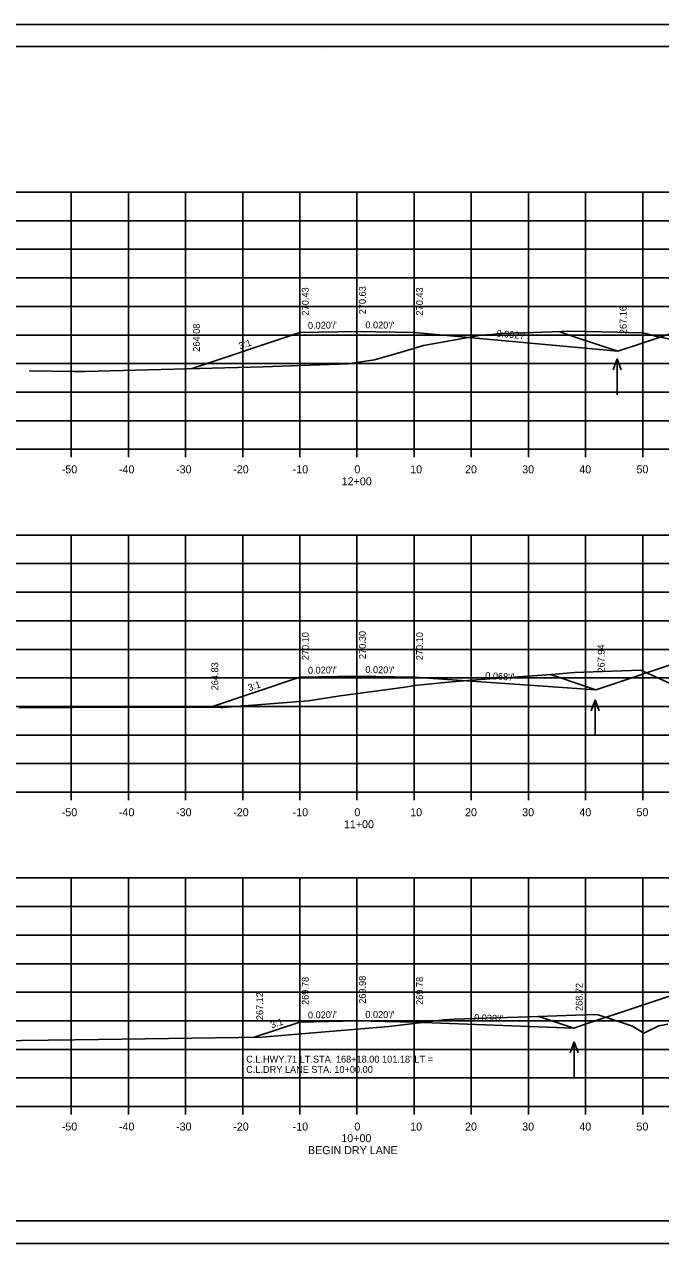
# Model space of a CAD drawing. Extents: x 285 to 4233, y -659 to 3710.
# Drawn here: x 4012.2 to 4123.5, y -579.2 to -365.9 of the extents above; entities that cross this region are included whole.
import ezdxf

# ---------------------------------------------------------------- set-up
doc = ezdxf.new("R2010")
doc.units = 0
for name, color, linetype in [('R_Axis', 7, 'Continuous'), ('R_Axis Annot', 7, 'Continuous'), ('R_Border', 7, 'Continuous'), ('R_Dimension', 7, 'Continuous'), ('R_Exist Surface', 7, 'Continuous'), ('R_Fin Surface', 7, 'Continuous'), ('R_Grid', 7, 'Continuous'), ('R_No Plot', 7, 'Continuous'), ('R_Water Annot', 7, 'Continuous'), ('R_Xsect Elev', 7, 'Continuous'), ('R_Xsect Slope', 7, 'Continuous')]:
    doc.layers.add(name, color=color, linetype=linetype)

msp = doc.modelspace()

# ---------------------------------------------------------------- linework, layer by layer
at = {"layer": 'R_Axis'}
for p, q in [((3920.38, -440.26), (4220.38, -440.26)), ((4020.38, -441.66), (4020.38, -440.26)), ((4030.38, -441.66), (4030.38, -440.26)), ((4040.38, -441.66), (4040.38, -440.26)), ((4050.38, -441.66), (4050.38, -440.26)), ((4060.38, -441.66), (4060.38, -440.26)), ((4070.38, -441.66), (4070.38, -440.26)), ((4080.38, -441.66), (4080.38, -440.26)), ((4090.38, -441.66), (4090.38, -440.26)), ((4100.38, -441.66), (4100.38, -440.26)), ((4110.38, -441.66), (4110.38, -440.26)), ((4120.38, -441.66), (4120.38, -440.26)), ((3920.38, -500.26), (4220.38, -500.26)), ((4020.38, -501.66), (4020.38, -500.26)), ((4030.38, -501.66), (4030.38, -500.26)), ((4040.38, -501.66), (4040.38, -500.26)), ((4050.38, -501.66), (4050.38, -500.26)), ((4060.38, -501.66), (4060.38, -500.26)), ((4070.38, -501.66), (4070.38, -500.26)), ((4080.38, -501.66), (4080.38, -500.26)), ((4090.38, -501.66), (4090.38, -500.26)), ((4100.38, -501.66), (4100.38, -500.26)), ((4110.38, -501.66), (4110.38, -500.26)), ((4120.38, -501.66), (4120.38, -500.26)), ((3920.38, -555.26), (4220.38, -555.26)), ((4020.38, -556.66), (4020.38, -555.26)), ((4030.38, -556.66), (4030.38, -555.26)), ((4040.38, -556.66), (4040.38, -555.26)), ((4050.38, -556.66), (4050.38, -555.26)), ((4060.38, -556.66), (4060.38, -555.26)), ((4070.38, -556.66), (4070.38, -555.26)), ((4080.38, -556.66), (4080.38, -555.26)), ((4090.38, -556.66), (4090.38, -555.26)), ((4100.38, -556.66), (4100.38, -555.26)), ((4110.38, -556.66), (4110.38, -555.26)), ((4120.38, -556.66), (4120.38, -555.26))]:
    msp.add_line(p, q, dxfattribs=at)
at = {"layer": 'R_Border'}
for p, q in [((3912.38, -369.8), (4228.56, -369.8)), ((4064.9, -370.06), (4064.9, -370.06)), ((4064.9, -370.06), (4064.9, -370.06)), ((4228.56, -575.26), (3912.38, -575.26))]:
    msp.add_line(p, q, dxfattribs=at)
at = {"layer": 'R_Exist Surface'}
for points in [[(4013.03, -426.54), (4020.86, -426.65), (4022.74, -426.67), (4053.98, -425.84), (4068.84, -425.28), (4071.04, -424.95), (4073.44, -424.61), (4078.09, -423.23), (4082, -422.11), (4088.89, -420.86), (4092.09, -420.31), (4093.92, -420.18), (4095.42, -419.97), (4101.32, -419.79), (4107.72, -419.6), (4115.91, -419.78), (4119.75, -419.85), (4120.2, -419.84), (4122.88, -420.53), (4131.19, -422.2)], [(4011.22, -485.44), (4020.63, -485.44), (4039.24, -485.38), (4046.57, -485.45), (4046.91, -485.42), (4061.87, -484.29), (4067.01, -483.45), (4077.08, -482.13), (4079.15, -481.79), (4080.47, -481.57), (4086.99, -480.96), (4091.29, -480.6), (4092.01, -480.55), (4104.42, -479.65), (4108.43, -479.32), (4110.06, -479.25), (4120.03, -478.92), (4122.49, -480.01), (4128.08, -482.59)], [(3997.6, -543.9), (4021.01, -543.58), (4053.78, -543.12), (4056.49, -542.88), (4075.95, -541.28), (4079.41, -540.84), (4085.58, -540.07), (4087.42, -539.99), (4090.99, -539.83), (4100.42, -539.56), (4111.94, -539.14), (4112.59, -539.22), (4115.09, -540.03), (4118.27, -541.08), (4118.41, -541.12), (4118.5, -541.15), (4120.58, -542.4), (4120.69, -542.36), (4123.2, -541.11), (4124.78, -540.84)]]:
    msp.add_lwpolyline(points, dxfattribs=at)
at = {"layer": 'R_Fin Surface'}
for points in [[(4105.7, -419.66), (4108.91, -420.73), (4116.01, -423.1), (4119.4, -421.97), (4142.06, -414.43), (4151.54, -412.86), (4162.1, -411.1), (4164.59, -411), (4170.11, -410.78), (4171.67, -410.75), (4172.12, -410.74), (4176.16, -410.66), (4189.76, -410.39), (4196.16, -410.26), (4196.68, -410.28), (4202.18, -410.5), (4217.15, -412.99), (4220.38, -413.53)], [(4041.34, -426.18), (4060.38, -419.83), (4070.38, -419.63), (4080.38, -419.83), (4116.01, -423.1)], [(4104.21, -479.67), (4105.82, -480.2), (4112.16, -482.32), (4114.8, -481.44), (4135.87, -474.43), (4145.96, -472.75), (4155.9, -471.1), (4158.68, -470.99), (4163.92, -470.78), (4165.4, -470.75), (4165.92, -470.74), (4170.68, -470.64), (4186.67, -470.32), (4189.97, -470.26), (4190.23, -470.27), (4195.98, -470.5), (4199.51, -471.09), (4218.21, -474.2)], [(4044.55, -485.43), (4060.38, -480.15), (4070.38, -479.95), (4080.38, -480.15), (4112.16, -482.32)], [(4102.17, -539.49), (4102.72, -539.68), (4108.31, -541.54), (4110.32, -540.87), (4129.67, -534.43), (4140.37, -532.65), (4149.71, -531.1), (4152.76, -530.98), (4157.72, -530.78), (4159.12, -530.75), (4159.73, -530.74), (4165.19, -530.63), (4183.57, -530.26), (4183.77, -530.26), (4183.79, -530.26), (4189.78, -530.5), (4192.25, -530.91), (4212.81, -534.33)], [(4052.41, -543.14), (4060.38, -540.48), (4070.38, -540.28), (4080.38, -540.48), (4108.31, -541.54)]]:
    msp.add_lwpolyline(points, dxfattribs=at)
at = {"layer": 'R_Grid'}
for p, q in [((3920.38, -395.26), (4220.38, -395.26)), ((4020.38, -440.26), (4020.38, -395.26)), ((4030.38, -440.26), (4030.38, -395.26)), ((4040.38, -440.26), (4040.38, -395.26)), ((4050.38, -440.26), (4050.38, -395.26)), ((4060.38, -440.26), (4060.38, -395.26)), ((4070.38, -440.26), (4070.38, -395.26)), ((4080.38, -440.26), (4080.38, -395.26)), ((4090.38, -440.26), (4090.38, -395.26)), ((4100.38, -440.26), (4100.38, -395.26)), ((4110.38, -440.26), (4110.38, -395.26)), ((4120.38, -440.26), (4120.38, -395.26)), ((3920.38, -400.26), (4220.38, -400.26)), ((3920.38, -405.26), (4220.38, -405.26)), ((3920.38, -410.26), (4220.38, -410.26)), ((3920.38, -415.26), (4220.38, -415.26)), ((3920.38, -420.26), (4220.38, -420.26)), ((3920.38, -425.26), (4220.38, -425.26)), ((3920.38, -430.26), (4220.38, -430.26)), ((3920.38, -435.26), (4220.38, -435.26)), ((3920.38, -440.26), (4220.38, -440.26)), ((3920.38, -455.26), (4220.38, -455.26)), ((4020.38, -500.26), (4020.38, -455.26)), ((4030.38, -500.26), (4030.38, -455.26)), ((4040.38, -500.26), (4040.38, -455.26)), ((4050.38, -500.26), (4050.38, -455.26)), ((4060.38, -500.26), (4060.38, -455.26)), ((4070.38, -500.26), (4070.38, -455.26)), ((4080.38, -500.26), (4080.38, -455.26)), ((4090.38, -500.26), (4090.38, -455.26)), ((4100.38, -500.26), (4100.38, -455.26)), ((4110.38, -500.26), (4110.38, -455.26)), ((4120.38, -500.26), (4120.38, -455.26)), ((3920.38, -460.26), (4220.38, -460.26)), ((3920.38, -465.26), (4220.38, -465.26)), ((3920.38, -470.26), (4220.38, -470.26)), ((3920.38, -475.26), (4220.38, -475.26)), ((3920.38, -480.26), (4220.38, -480.26)), ((3920.38, -485.26), (4220.38, -485.26)), ((3920.38, -490.26), (4220.38, -490.26)), ((3920.38, -495.26), (4220.38, -495.26)), ((3920.38, -500.26), (4220.38, -500.26)), ((3920.38, -515.26), (4220.38, -515.26)), ((4020.38, -555.26), (4020.38, -515.26)), ((4030.38, -555.26), (4030.38, -515.26)), ((4040.38, -555.26), (4040.38, -515.26)), ((4050.38, -555.26), (4050.38, -515.26)), ((4060.38, -555.26), (4060.38, -515.26)), ((4070.38, -555.26), (4070.38, -515.26)), ((4080.38, -555.26), (4080.38, -515.26)), ((4090.38, -555.26), (4090.38, -515.26)), ((4100.38, -555.26), (4100.38, -515.26)), ((4110.38, -555.26), (4110.38, -515.26)), ((4120.38, -555.26), (4120.38, -515.26)), ((3920.38, -520.26), (4220.38, -520.26)), ((3920.38, -525.26), (4220.38, -525.26)), ((3920.38, -530.26), (4220.38, -530.26)), ((3920.38, -535.26), (4220.38, -535.26)), ((3920.38, -540.26), (4220.38, -540.26)), ((3920.38, -545.26), (4220.38, -545.26)), ((3920.38, -550.26), (4220.38, -550.26)), ((3920.38, -555.26), (4220.38, -555.26))]:
    msp.add_line(p, q, dxfattribs=at)
at = {"layer": 'R_No Plot'}
for p, q in [((3899.98, -365.9), (4233.31, -365.9)), ((3899.98, -579.24), (4233.31, -579.24))]:
    msp.add_line(p, q, dxfattribs=at)
for points in [[(3899.97, -365.9), (4233.31, -365.9), (4233.31, -579.24), (3899.97, -579.24)], [(4146.3, -369.8), (4165.92, -369.8), (4165.92, -379.68), (4182.03, -379.68), (4205.23, -379.68), (4205.35, -407.84), (4228.56, -407.84), (4228.56, -575.26), (3912.38, -575.26), (3912.38, -369.8)]]:
    msp.add_lwpolyline(points, close=True, dxfattribs=at)
at = {"layer": 'R_Water Annot'}
for p, q in [((4115.94, -424.42), (4115.24, -426.34)), ((4115.94, -430.7), (4115.94, -424.42)), ((4115.94, -424.42), (4116.64, -426.34)), ((4112.08, -484.11), (4111.38, -486.04)), ((4112.08, -490.4), (4112.08, -484.11)), ((4112.08, -484.11), (4112.78, -486.04)), ((4108.36, -543.91), (4107.66, -545.83)), ((4108.36, -550.19), (4108.36, -543.91)), ((4108.36, -543.91), (4109.06, -545.83))]:
    msp.add_line(p, q, dxfattribs=at)

# ---------------------------------------------------------------- texts
at = {"layer": 'R_Axis Annot'}
for s, p in [('-50', (4018.72, -444.46)), ('-40', (4028.72, -444.46)), ('-30', (4038.72, -444.46)), ('-20', (4048.72, -444.46)), ('-10', (4059.12, -444.46)), ('0', (4069.92, -444.46)), ('10', (4079.69, -444.46)), ('20', (4089.29, -444.46)), ('30', (4099.29, -444.46)), ('40', (4109.29, -444.46)), ('50', (4119.29, -444.46)), ('12+00', (4067.7, -446.56)), ('-50', (4018.72, -504.46)), ('-40', (4028.72, -504.46)), ('-30', (4038.72, -504.46)), ('-20', (4048.72, -504.46)), ('-10', (4059.12, -504.46)), ('0', (4069.92, -504.46)), ('10', (4079.69, -504.46)), ('20', (4089.29, -504.46)), ('30', (4099.29, -504.46)), ('40', (4109.29, -504.46)), ('50', (4119.29, -504.46)), ('11+00', (4068.09, -506.56)), ('-50', (4018.72, -559.46)), ('-40', (4028.72, -559.46)), ('-30', (4038.72, -559.46)), ('-20', (4048.72, -559.46)), ('-10', (4059.12, -559.46)), ('0', (4069.92, -559.46)), ('10', (4079.69, -559.46)), ('20', (4089.29, -559.46)), ('30', (4099.29, -559.46)), ('40', (4109.29, -559.46)), ('50', (4119.29, -559.46)), ('10+00', (4067.64, -561.49)), ('BEGIN DRY LANE', (4061.8, -563.59))]:
    msp.add_text(s, height=1.4, dxfattribs=at).set_placement(p)
at = {"layer": 'R_Dimension'}
for s, p in [("C.L.HWY.71 LT.STA. 168+18.00 101.18' LT =", (4050.99, -547.57)), ('C.L.DRY LANE STA. 10+00.00', (4050.99, -549.37))]:
    msp.add_text(s, height=1.2, dxfattribs=at).set_placement(p)
at = {"layer": 'R_Xsect Elev'}
for s, p in [('270.43', (4061.93, -416.83)), ('270.63', (4071.93, -416.63)), ('270.43', (4081.93, -416.83)), ('267.16', (4117.56, -420.1)), ('264.08', (4042.89, -423.18)), ('270.10', (4061.93, -477.15)), ('270.30', (4071.93, -476.95)), ('270.10', (4081.93, -477.15)), ('267.94', (4113.71, -479.32)), ('264.83', (4046.1, -482.43)), ('269.78', (4061.93, -537.48)), ('269.98', (4071.93, -537.28)), ('269.78', (4081.93, -537.48)), ('267.12', (4053.96, -540.14)), ('268.72', (4109.86, -538.54))]:
    msp.add_text(s, height=1.2, rotation=90, dxfattribs=at).set_placement(p)
at = {"layer": 'R_Xsect Slope'}
for s, rotation, p in [("0.020'/'", 1.1458, (4061.81, -419.2)), ("0.020'/'", 358.8542, (4071.83, -419.06)), ("0.092'/'", 354.7563, (4094.75, -420.54)), ('3:1', 18.4349, (4049.91, -422.79)), ("0.020'/'", 1.1458, (4061.81, -479.53)), ("0.020'/'", 358.8542, (4071.83, -479.38)), ("0.068'/'", 356.103, (4092.78, -480.4)), ('3:1', 18.4349, (4051.52, -482.58)), ("0.020'/'", 1.1458, (4061.81, -539.85)), ("0.020'/'", 358.8542, (4071.83, -539.71)), ("0.038'/'", 357.8275, (4090.85, -540.28)), ('3:1', 18.4349, (4055.45, -541.6))]:
    msp.add_text(s, height=1.2, rotation=rotation, dxfattribs=at).set_placement(p)

doc.saveas('drawing.dxf')
